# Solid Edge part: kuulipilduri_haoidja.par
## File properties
Author: Georg
Template: Iso Metric Part.par
Last saved by: Georg
Revision: 3
Application: Solid Edge
Accuracy: 0,990
Face Style: Model Default
Fill Style: Normal
Coef. of Thermal Exp: 0.0
Thermal Conductivity: 0.0
Specific Heat: 0.0
Modulus of Elasticity: 0.0
Poisson's Ratio: 0.0
Yield Stress: 0.0
Ultimate Stress: 0.0
Elongation: 0.0
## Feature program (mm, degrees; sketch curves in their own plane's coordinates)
sketch for "ExtrudedProtrusion_1" #1 plane through (0, 0, -170) normal (0, 0, 1) x-axis (1, 0, 0)
  line (37.5, 4470.2777) -> (37.5, 4370.2777)
  line (37.5, 4370.2777) -> (62.5, 4370.2777)
  line (62.5, 4370.2777) -> (62.5, 4470.2777)
  line (62.5, 4470.2777) -> (37.5, 4470.2777)
sketch for "ExtrudedProtrusion_1" #2 plane through (0, 0, -170) normal (0, 0, 1) x-axis (1, 0, 0)
  line (-37.5, 4370.2777) -> (-37.5, 4470.2777)
  line (-37.5, 4470.2777) -> (-62.5, 4470.2777)
  line (-62.5, 4470.2777) -> (-62.5, 4370.2777)
  line (-62.5, 4370.2777) -> (-37.5, 4370.2777)
extrude "ExtrudedProtrusion_1" add finite 550 along -normal
sketch for "ExtrudedCutout_1" #1 plane through (-62.5, 4420.2777, -445) normal (-1, 0, 0) x-axis (0, 0, -1)
  circle centre (175, 0) radius 15
sketch for "ExtrudedCutout_1" #2 plane through (-62.5, 4420.2777, -445) normal (-1, 0, 0) x-axis (0, 0, -1)
  arc centre (175.3398, 0.0006) radius 50.0006 from (175.3398, -50) to (225.3404, 0) ccw
  arc centre (175, -0.3415) radius 50.3415 from (175, 50) to (225.3404, 0) cw
  line (275, 50) -> (175, 50)
  line (275, -50) -> (275, 50)
  line (175.3398, -50) -> (275, -50)
extrude "ExtrudedCutout_1" cut finite 242.4543 along -normal
sketch for "ExtrudedCutout_2" plane through (-62.5, 4420.2777, -420.1702) normal (-1, 0, 0) x-axis (0, 0, -1)
  line (-105.3325, 50) -> (-105.3325, -50)
  line (-105.3325, -50) -> (-250.1702, -50)
  line (-250.1702, 50) -> (-250.1702, -50)
  line (-240.9995, 50) -> (-250.1702, 50)
  line (-240.9995, 50) -> (-105.3325, 50)
extrude "ExtrudedCutout_2" cut finite 2189.5772 along -normal
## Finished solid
Body 1: solid body, 16 faces, 34 edges, 20 vertices, 2 separate solids.
  Faces by surface: plane 10, cylinder 6
  Edges by curve: line 22, circle 12
Bounding box of the edges (mm): 125.000 x 100.000 x 355.503, from (-62.5, 4370.2777, -670.3404) to (62.5, 4470.2777, -314.8377).
Cylindrical faces by radius (mm): R15 x2, R50.0006 x2, R50.3415 x2
Planar faces by outward normal: +x 2, +y 2, +z 2, -x 2, -y 2
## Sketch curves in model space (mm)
line (62.5, 4370.2777, -170) -> (62.5, 4470.2777, -170)
line (62.5, 4470.2777, -170) -> (37.5, 4470.2777, -170)
line (37.5, 4470.2777, -170) -> (37.5, 4370.2777, -170)
line (37.5, 4370.2777, -170) -> (62.5, 4370.2777, -170)
line (-62.5, 4470.2777, -170) -> (-62.5, 4370.2777, -170)
line (-62.5, 4370.2777, -170) -> (-37.5, 4370.2777, -170)
line (-37.5, 4370.2777, -170) -> (-37.5, 4470.2777, -170)
line (-37.5, 4470.2777, -170) -> (-62.5, 4470.2777, -170)
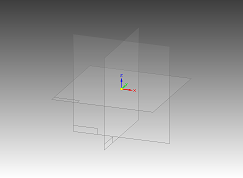
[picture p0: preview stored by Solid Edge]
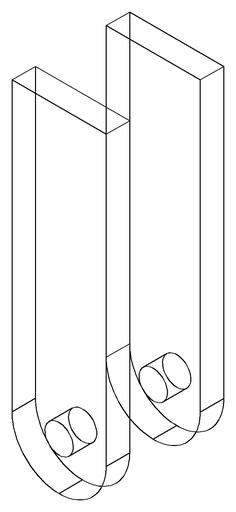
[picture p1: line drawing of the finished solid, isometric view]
